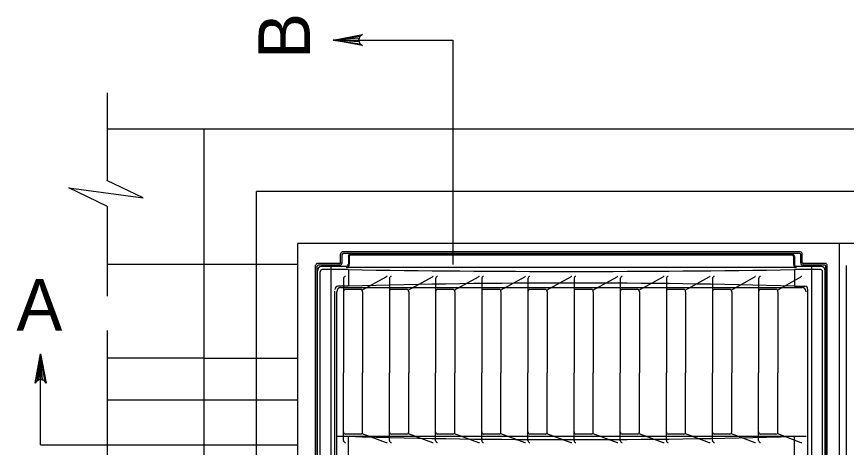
# Model space of a CAD drawing. Extents: x 6.91 to 13.84, y 0.35 to 9.99.
# Drawn here: x 7.032 to 8.644, y 9.125 to 9.961 of the extents above; entities that cross this region are included whole.
import ezdxf

# ---------------------------------------------------------------- set-up
doc = ezdxf.new("R2010")
doc.units = 0
for name, color, linetype in [('DETL-DIMS', 7, 'Continuous'), ('DETL-LINE', 7, 'Continuous'), ('DETL-NOTE', 7, 'Continuous'), ('DETL-TITL', 7, 'Continuous')]:
    doc.layers.add(name, color=color, linetype=linetype)

msp = doc.modelspace()

# ---------------------------------------------------------------- linework, layer by layer
at = {"layer": 'DETL-DIMS'}
for p, q in [((7.6472, 9.9156), (7.8795, 9.9156)), ((7.8795, 9.9156), (7.8795, 9.4798)), ((7.0784, 9.1301), (7.0784, 9.3062)), ((7.0784, 9.1301), (7.5785, 9.1301))]:
    msp.add_line(p, q, dxfattribs=at)
for points in [[(7.6472, 9.9156), (7.7037, 9.9262), (7.6994, 9.9232), (7.6971, 9.9194), (7.6965, 9.9156), (7.6971, 9.9118), (7.6994, 9.908), (7.7037, 9.905), (7.6472, 9.9156), (7.6994, 9.908), (7.6971, 9.9118), (7.6472, 9.9156), (7.6965, 9.9156), (7.6971, 9.9194), (7.6472, 9.9156), (7.6994, 9.9232)], [(7.0784, 9.3062), (7.089, 9.2496), (7.086, 9.254), (7.0822, 9.2562), (7.0784, 9.2569), (7.0746, 9.2562), (7.0708, 9.254), (7.0678, 9.2496), (7.0784, 9.3062), (7.0708, 9.254), (7.0746, 9.2562), (7.0784, 9.3062), (7.0784, 9.2569), (7.0822, 9.2562), (7.0784, 9.3062), (7.086, 9.254)]]:
    msp.add_lwpolyline(points, dxfattribs=at)
at = {"layer": 'DETL-LINE'}
for p, q in [((7.2076, 9.8131), (7.2076, 9.6428)), ((10.1347, 9.7427), (7.2076, 9.7427)), ((7.3965, 8.1996), (7.3965, 9.7427)), ((9.7629, 9.6214), (7.4976, 9.6214)), ((7.4976, 8.3007), (7.4976, 9.6214)), ((7.4976, 9.4798), (7.4976, 9.6214)), ((7.2076, 9.5928), (7.2076, 9.4186)), ((9.682, 9.5203), (7.5785, 9.5203)), ((7.5785, 8.4019), (7.5785, 9.5203)), ((8.6303, 9.5203), (8.6303, 8.4019)), ((7.6614, 9.484), (7.6614, 9.4999)), ((7.6642, 9.4829), (7.6642, 9.4989)), ((8.5546, 9.5042), (7.6652, 9.5042)), ((8.5537, 9.501), (7.6661, 9.501)), ((8.5555, 9.4829), (8.5555, 9.4989)), ((8.5583, 9.484), (8.5583, 9.4999)), ((7.6781, 9.4956), (7.6781, 9.4803)), ((8.5396, 9.4979), (7.6801, 9.4979)), ((8.5416, 9.4956), (8.5416, 9.4803)), ((7.5785, 9.4798), (7.2076, 9.4798)), ((7.6128, 8.4504), (7.6128, 9.4776)), ((7.6156, 8.4514), (7.6156, 9.4765)), ((7.6596, 9.4819), (7.6166, 9.4819)), ((7.6605, 9.4787), (7.6175, 9.4787)), ((7.6764, 9.4699), (7.6256, 9.4699)), ((7.6427, 9.476), (7.6427, 9.4787)), ((7.6427, 8.4495), (7.6427, 9.476)), ((8.5471, 9.4739), (7.6733, 9.4739)), ((7.6764, 9.4699), (7.6764, 9.4377)), ((8.5941, 9.4699), (8.5434, 9.4699)), ((8.5434, 9.4699), (8.5434, 9.4377)), ((8.6022, 9.4787), (8.5593, 9.4787)), ((8.6032, 9.4819), (8.5602, 9.4819)), ((8.577, 9.476), (8.577, 9.4787)), ((8.577, 8.4495), (8.577, 9.476)), ((8.6041, 8.4514), (8.6041, 9.4765)), ((8.6069, 8.4504), (8.6069, 9.4776)), ((8.6443, 8.4504), (8.6443, 9.4776)), ((7.6219, 8.4599), (7.6219, 9.4656)), ((8.5979, 8.4599), (8.5979, 9.4656)), ((7.6764, 9.4377), (7.6559, 9.4377)), ((7.6614, 9.4353), (8.5583, 9.4353)), ((8.5434, 9.4377), (8.5638, 9.4377)), ((7.6503, 8.4942), (7.6503, 9.4278)), ((7.6539, 8.4988), (7.6539, 9.4267)), ((8.5694, 8.4942), (8.5694, 9.4313)), ((7.2076, 9.3519), (7.2076, 9.0456)), ((7.3965, 9.2978), (7.2076, 9.2978)), ((7.3965, 9.2978), (7.5785, 9.2978)), ((7.2076, 9.2169), (7.5785, 9.2169)), ((8.5658, 9.1463), (7.6539, 9.1463)), ((7.6764, 9.1074), (7.6764, 9.1463)), ((8.5434, 9.1074), (8.5434, 9.1463))]:
    msp.add_line(p, q, dxfattribs=at)
msp.add_lwpolyline([(7.2071, 9.5928), (7.1334, 9.6289), (7.2777, 9.6092), (7.2071, 9.6428)], dxfattribs=at)
for centre, major_axis, start_param, end_param in [((7.6652, 9.4999), (0, 0.0043), 0, 1.570796), ((7.6661, 9.4989), (0, 0.00215), 0, 1.570796), ((8.5537, 9.4989), (0, 0.00215), 4.712389, 6.283185), ((8.5546, 9.4999), (0, 0.0043), 4.712389, 6.283185), ((7.6596, 9.484), (0, 0.00215), 3.141593, 4.712389), ((7.6605, 9.4829), (0, 0.0043), 3.141593, 4.712389), ((7.6801, 9.4956), (0, 0.00227), 0, 1.570796), ((8.5396, 9.4956), (0, 0.00227), 4.712389, 6.283185), ((8.5593, 9.4829), (0, 0.0043), 1.570796, 3.141593), ((8.5602, 9.484), (0, 0.00215), 1.570796, 3.141593), ((7.6166, 9.4776), (0, 0.0043), 0, 1.570796), ((7.6175, 9.4765), (0, 0.00215), 0, 1.570796), ((7.6256, 9.4656), (0, 0.0043), 0, 1.570796), ((7.6726, 9.4803), (0, 0.00632), 3.141593, 4.712389), ((8.1099, 45.6115), (0, 36.1451), 3.1278, 3.155386), ((8.5471, 9.4803), (0, 0.00632), 1.570796, 3.141593), ((8.5941, 9.4656), (0, 0.0043), 4.712389, 6.283185), ((8.6022, 9.4765), (0, 0.00215), 4.712389, 6.283185), ((8.6032, 9.4776), (0, 0.0043), 4.712389, 6.283185), ((7.6559, 9.4313), (0, 0.00645), 0, 1.570796), ((7.6614, 9.4267), (0, 0.0086), 0, 1.570796), ((8.1099, -10.7224), (0, 20.1663), 6.258462, 6.307909), ((8.5583, 9.4267), (0, 0.0086), 4.712389, 6.283185), ((8.5638, 9.4313), (0, 0.00645), 4.712389, 6.283185), ((8.1099, 28.4196), (0, 19.2797), 3.115732, 3.167453)]:
    msp.add_ellipse(centre, major_axis=major_axis, ratio=0.869565, start_param=start_param, end_param=end_param, dxfattribs=at)
at = {"layer": 'DETL-NOTE'}
for p, q in [((7.6801, 9.4999), (8.5396, 9.4999)), ((7.6764, 9.4956), (7.6764, 9.4803)), ((7.6764, 9.4846), (7.6764, 9.4804)), ((8.5434, 9.4956), (8.5434, 9.4803)), ((7.6166, 8.4581), (7.6166, 9.4674)), ((7.6726, 9.476), (7.624, 9.476)), ((8.5957, 9.476), (8.5471, 9.476)), ((8.6032, 8.4581), (8.6032, 9.4674)), ((7.667, 9.4523), (7.667, 9.2697)), ((7.7029, 9.4302), (7.75, 9.4562)), ((7.7562, 9.4523), (7.7562, 9.2697)), ((7.7926, 9.4302), (7.8397, 9.4562)), ((7.8459, 9.4523), (7.8459, 9.2697)), ((7.8823, 9.4302), (7.9294, 9.4562)), ((7.9356, 9.4523), (7.9356, 9.2697)), ((7.9719, 9.4302), (8.0191, 9.4562)), ((8.0253, 9.4523), (8.0253, 9.2697)), ((8.0616, 9.4302), (8.1088, 9.4562)), ((8.115, 9.4523), (8.115, 9.2697)), ((8.1513, 9.4302), (8.1985, 9.4562)), ((8.2047, 9.4523), (8.2047, 9.2697)), ((8.241, 9.4302), (8.2881, 9.4562)), ((8.2944, 9.4523), (8.2944, 9.2697)), ((8.3307, 9.4302), (8.3778, 9.4562)), ((8.3841, 9.4523), (8.3841, 9.2697)), ((8.4204, 9.4302), (8.4661, 9.4562)), ((8.4737, 9.4523), (8.4737, 9.2697)), ((8.5101, 9.4302), (8.5558, 9.4562)), ((7.7002, 9.4314), (7.6707, 9.4314)), ((7.704, 9.4271), (7.704, 9.2697)), ((7.7899, 9.4314), (7.76, 9.4314)), ((7.7937, 9.4271), (7.7937, 9.2697)), ((7.8796, 9.4314), (7.8496, 9.4314)), ((7.8834, 9.4271), (7.8834, 9.2697)), ((7.9693, 9.4314), (7.9393, 9.4314)), ((7.973, 9.4271), (7.973, 9.2697)), ((8.059, 9.4314), (8.029, 9.4314)), ((8.0627, 9.4271), (8.0627, 9.2697)), ((8.1487, 9.4314), (8.1187, 9.4314)), ((8.1524, 9.4271), (8.1524, 9.2697)), ((8.2384, 9.4314), (8.2084, 9.4314)), ((8.2421, 9.4271), (8.2421, 9.2697)), ((8.3281, 9.4314), (8.2981, 9.4314)), ((8.3318, 9.4271), (8.3318, 9.2697)), ((8.4178, 9.4314), (8.3878, 9.4314)), ((8.4215, 9.4271), (8.4215, 9.2697)), ((8.5074, 9.4314), (8.4775, 9.4314)), ((8.5112, 9.4271), (8.5112, 9.2697)), ((7.667, 9.1384), (7.667, 9.2697)), ((7.704, 9.1549), (7.704, 9.2697)), ((7.7562, 9.1384), (7.7562, 9.2697)), ((7.7937, 9.1549), (7.7937, 9.2697)), ((7.8459, 9.1384), (7.8459, 9.2697)), ((7.8834, 9.1549), (7.8834, 9.2697)), ((7.9356, 9.1384), (7.9356, 9.2697)), ((7.973, 9.1549), (7.973, 9.2697)), ((8.0253, 9.1384), (8.0253, 9.2697)), ((8.0627, 9.1549), (8.0627, 9.2697)), ((8.115, 9.1384), (8.115, 9.2697)), ((8.1524, 9.1549), (8.1524, 9.2697)), ((8.2047, 9.1384), (8.2047, 9.2697)), ((8.2421, 9.1549), (8.2421, 9.2697)), ((8.2944, 9.1384), (8.2944, 9.2697)), ((8.3318, 9.1549), (8.3318, 9.2697)), ((8.3841, 9.1384), (8.3841, 9.2697)), ((8.4215, 9.1549), (8.4215, 9.2697)), ((8.4737, 9.1384), (8.4737, 9.2697)), ((8.5112, 9.1549), (8.5112, 9.2697)), ((7.7002, 9.1506), (7.6707, 9.1506)), ((7.7029, 9.1519), (7.75, 9.1345)), ((7.7899, 9.1506), (7.76, 9.1506)), ((7.7926, 9.1519), (7.8397, 9.1345)), ((7.8796, 9.1506), (7.8496, 9.1506)), ((7.8823, 9.1519), (7.9294, 9.1345)), ((7.9693, 9.1506), (7.9393, 9.1506)), ((7.9719, 9.1519), (8.0191, 9.1345)), ((8.059, 9.1506), (8.029, 9.1506)), ((8.0616, 9.1519), (8.1088, 9.1345)), ((8.1487, 9.1506), (8.1187, 9.1506)), ((8.1513, 9.1519), (8.1985, 9.1345)), ((8.2384, 9.1506), (8.2084, 9.1506)), ((8.241, 9.1519), (8.2881, 9.1345)), ((8.3281, 9.1506), (8.2981, 9.1506)), ((8.3307, 9.1519), (8.3778, 9.1345)), ((8.4178, 9.1506), (8.3878, 9.1506)), ((8.4204, 9.1519), (8.4661, 9.1345)), ((8.5074, 9.1506), (8.4775, 9.1506)), ((8.5101, 9.1519), (8.5558, 9.1345))]:
    msp.add_line(p, q, dxfattribs=at)
for centre, major_axis, start_param, end_param in [((7.6801, 9.4956), (0, 0.0043), 0, 1.570796), ((8.5396, 9.4956), (0, 0.0043), 4.712389, 6.283185), ((7.624, 9.4674), (0, 0.0086), 0, 1.570796), ((7.6726, 9.4803), (0, 0.0043), 3.141593, 4.712389), ((8.5471, 9.4803), (0, 0.0043), 1.570796, 3.141593), ((8.5957, 9.4674), (0, 0.0086), 4.712389, 6.283185), ((7.6707, 9.4523), (0, 0.0043), 0, 1.570796), ((7.7516, 9.4523), (0, 0.0043), 0, 0.447297), ((7.76, 9.4523), (0, 0.0043), 0, 1.570796), ((7.8413, 9.4523), (0, 0.0043), 0, 0.447297), ((7.8496, 9.4523), (0, 0.0043), 0, 1.570796), ((7.931, 9.4523), (0, 0.0043), 0, 0.447297), ((7.9393, 9.4523), (0, 0.0043), 0, 1.570796), ((8.0207, 9.4523), (0, 0.0043), 0, 0.447297), ((8.029, 9.4523), (0, 0.0043), 0, 1.570796), ((8.1104, 9.4523), (0, 0.0043), 0, 0.447297), ((8.1187, 9.4523), (0, 0.0043), 0, 1.570796), ((8.2001, 9.4523), (0, 0.0043), 0, 0.447297), ((8.2084, 9.4523), (0, 0.0043), 0, 1.570796), ((8.2898, 9.4523), (0, 0.0043), 0, 0.447297), ((8.2981, 9.4523), (0, 0.0043), 0, 1.570796), ((8.3795, 9.4523), (0, 0.0043), 0, 0.447297), ((8.3878, 9.4523), (0, 0.0043), 0, 1.570796), ((8.4678, 9.4523), (0, 0.0043), 0, 0.447297), ((8.4775, 9.4523), (0, 0.0043), 0, 1.570796), ((8.5575, 9.4523), (0, 0.0043), 0, 0.447297), ((7.6707, 9.4271), (0, 0.0043), 0, 1.570796), ((7.7002, 9.4271), (0, 0.0043), 4.712389, 6.283185), ((7.76, 9.4271), (0, 0.0043), 0, 1.570796), ((7.7899, 9.4271), (0, 0.0043), 4.712389, 6.283185), ((7.8496, 9.4271), (0, 0.0043), 0, 1.570796), ((7.8796, 9.4271), (0, 0.0043), 4.712389, 6.283185), ((7.9393, 9.4271), (0, 0.0043), 0, 1.570796), ((7.9693, 9.4271), (0, 0.0043), 4.712389, 6.283185), ((8.029, 9.4271), (0, 0.0043), 0, 1.570796), ((8.059, 9.4271), (0, 0.0043), 4.712389, 6.283185), ((8.1187, 9.4271), (0, 0.0043), 0, 1.570796), ((8.1487, 9.4271), (0, 0.0043), 4.712389, 6.283185), ((8.2084, 9.4271), (0, 0.0043), 0, 1.570796), ((8.2384, 9.4271), (0, 0.0043), 4.712389, 6.283185), ((8.2981, 9.4271), (0, 0.0043), 0, 1.570796), ((8.3281, 9.4271), (0, 0.0043), 4.712389, 6.283185), ((8.3878, 9.4271), (0, 0.0043), 0, 1.570796), ((8.4178, 9.4271), (0, 0.0043), 4.712389, 6.283185), ((8.4775, 9.4271), (0, 0.0043), 0, 1.570796), ((8.5074, 9.4271), (0, 0.0043), 4.712389, 6.283185), ((7.6707, 9.1549), (0, 0.0043), 1.570796, 3.141593), ((7.7002, 9.1549), (0, 0.0043), 3.141593, 4.712389), ((7.76, 9.1549), (0, 0.0043), 1.570796, 3.141593), ((7.7899, 9.1549), (0, 0.0043), 3.141593, 4.712389), ((7.8496, 9.1549), (0, 0.0043), 1.570796, 3.141593), ((7.8796, 9.1549), (0, 0.0043), 3.141593, 4.712389), ((7.9393, 9.1549), (0, 0.0043), 1.570796, 3.141593), ((7.9693, 9.1549), (0, 0.0043), 3.141593, 4.712389), ((8.029, 9.1549), (0, 0.0043), 1.570796, 3.141593), ((8.059, 9.1549), (0, 0.0043), 3.141593, 4.712389), ((8.1187, 9.1549), (0, 0.0043), 1.570796, 3.141593), ((8.1487, 9.1549), (0, 0.0043), 3.141593, 4.712389), ((8.2084, 9.1549), (0, 0.0043), 1.570796, 3.141593), ((8.2384, 9.1549), (0, 0.0043), 3.141593, 4.712389), ((8.2981, 9.1549), (0, 0.0043), 1.570796, 3.141593), ((8.3281, 9.1549), (0, 0.0043), 3.141593, 4.712389), ((8.3878, 9.1549), (0, 0.0043), 1.570796, 3.141593), ((8.4178, 9.1549), (0, 0.0043), 3.141593, 4.712389), ((8.4775, 9.1549), (0, 0.0043), 1.570796, 3.141593), ((8.5074, 9.1549), (0, 0.0043), 3.141593, 4.712389), ((7.6707, 9.1384), (0, 0.0043), 1.570796, 3.141593), ((7.7516, 9.1384), (0, 0.0043), 2.694296, 3.141593), ((7.76, 9.1384), (0, 0.0043), 1.570796, 3.141593), ((7.8413, 9.1384), (0, 0.0043), 2.694296, 3.141593), ((7.8496, 9.1384), (0, 0.0043), 1.570796, 3.141593), ((7.931, 9.1384), (0, 0.0043), 2.694296, 3.141593), ((7.9393, 9.1384), (0, 0.0043), 1.570796, 3.141593), ((8.0207, 9.1384), (0, 0.0043), 2.694296, 3.141593), ((8.029, 9.1384), (0, 0.0043), 1.570796, 3.141593), ((8.1104, 9.1384), (0, 0.0043), 2.694296, 3.141593), ((8.1187, 9.1384), (0, 0.0043), 1.570796, 3.141593), ((8.2001, 9.1384), (0, 0.0043), 2.694296, 3.141593), ((8.2084, 9.1384), (0, 0.0043), 1.570796, 3.141593), ((8.2898, 9.1384), (0, 0.0043), 2.694296, 3.141593), ((8.2981, 9.1384), (0, 0.0043), 1.570796, 3.141593), ((8.3795, 9.1384), (0, 0.0043), 2.694296, 3.141593), ((8.3878, 9.1384), (0, 0.0043), 1.570796, 3.141593), ((8.4678, 9.1384), (0, 0.0043), 2.694296, 3.141593), ((8.4775, 9.1384), (0, 0.0043), 1.570796, 3.141593), ((8.5575, 9.1384), (0, 0.0043), 2.694296, 3.141593)]:
    msp.add_ellipse(centre, major_axis=major_axis, ratio=0.869565, start_param=start_param, end_param=end_param, dxfattribs=at)

# ---------------------------------------------------------------- texts
at = {"layer": 'DETL-TITL'}
msp.add_text('B', height=0.1, rotation=90, dxfattribs=at).set_placement((7.6017, 9.8789))
msp.add_text('A', height=0.1, dxfattribs=at).set_placement((7.0314, 9.3517))

doc.saveas('drawing.dxf')
